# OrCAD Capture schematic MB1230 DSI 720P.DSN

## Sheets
1 mb1230: size A4; title: MB1230: 1280 x 720p DSI  LCD; rev: C02; company: ST MICROELECTRONICS; note: MB1230: 1280 x 720p DSI LCD; note: MDG/GPM
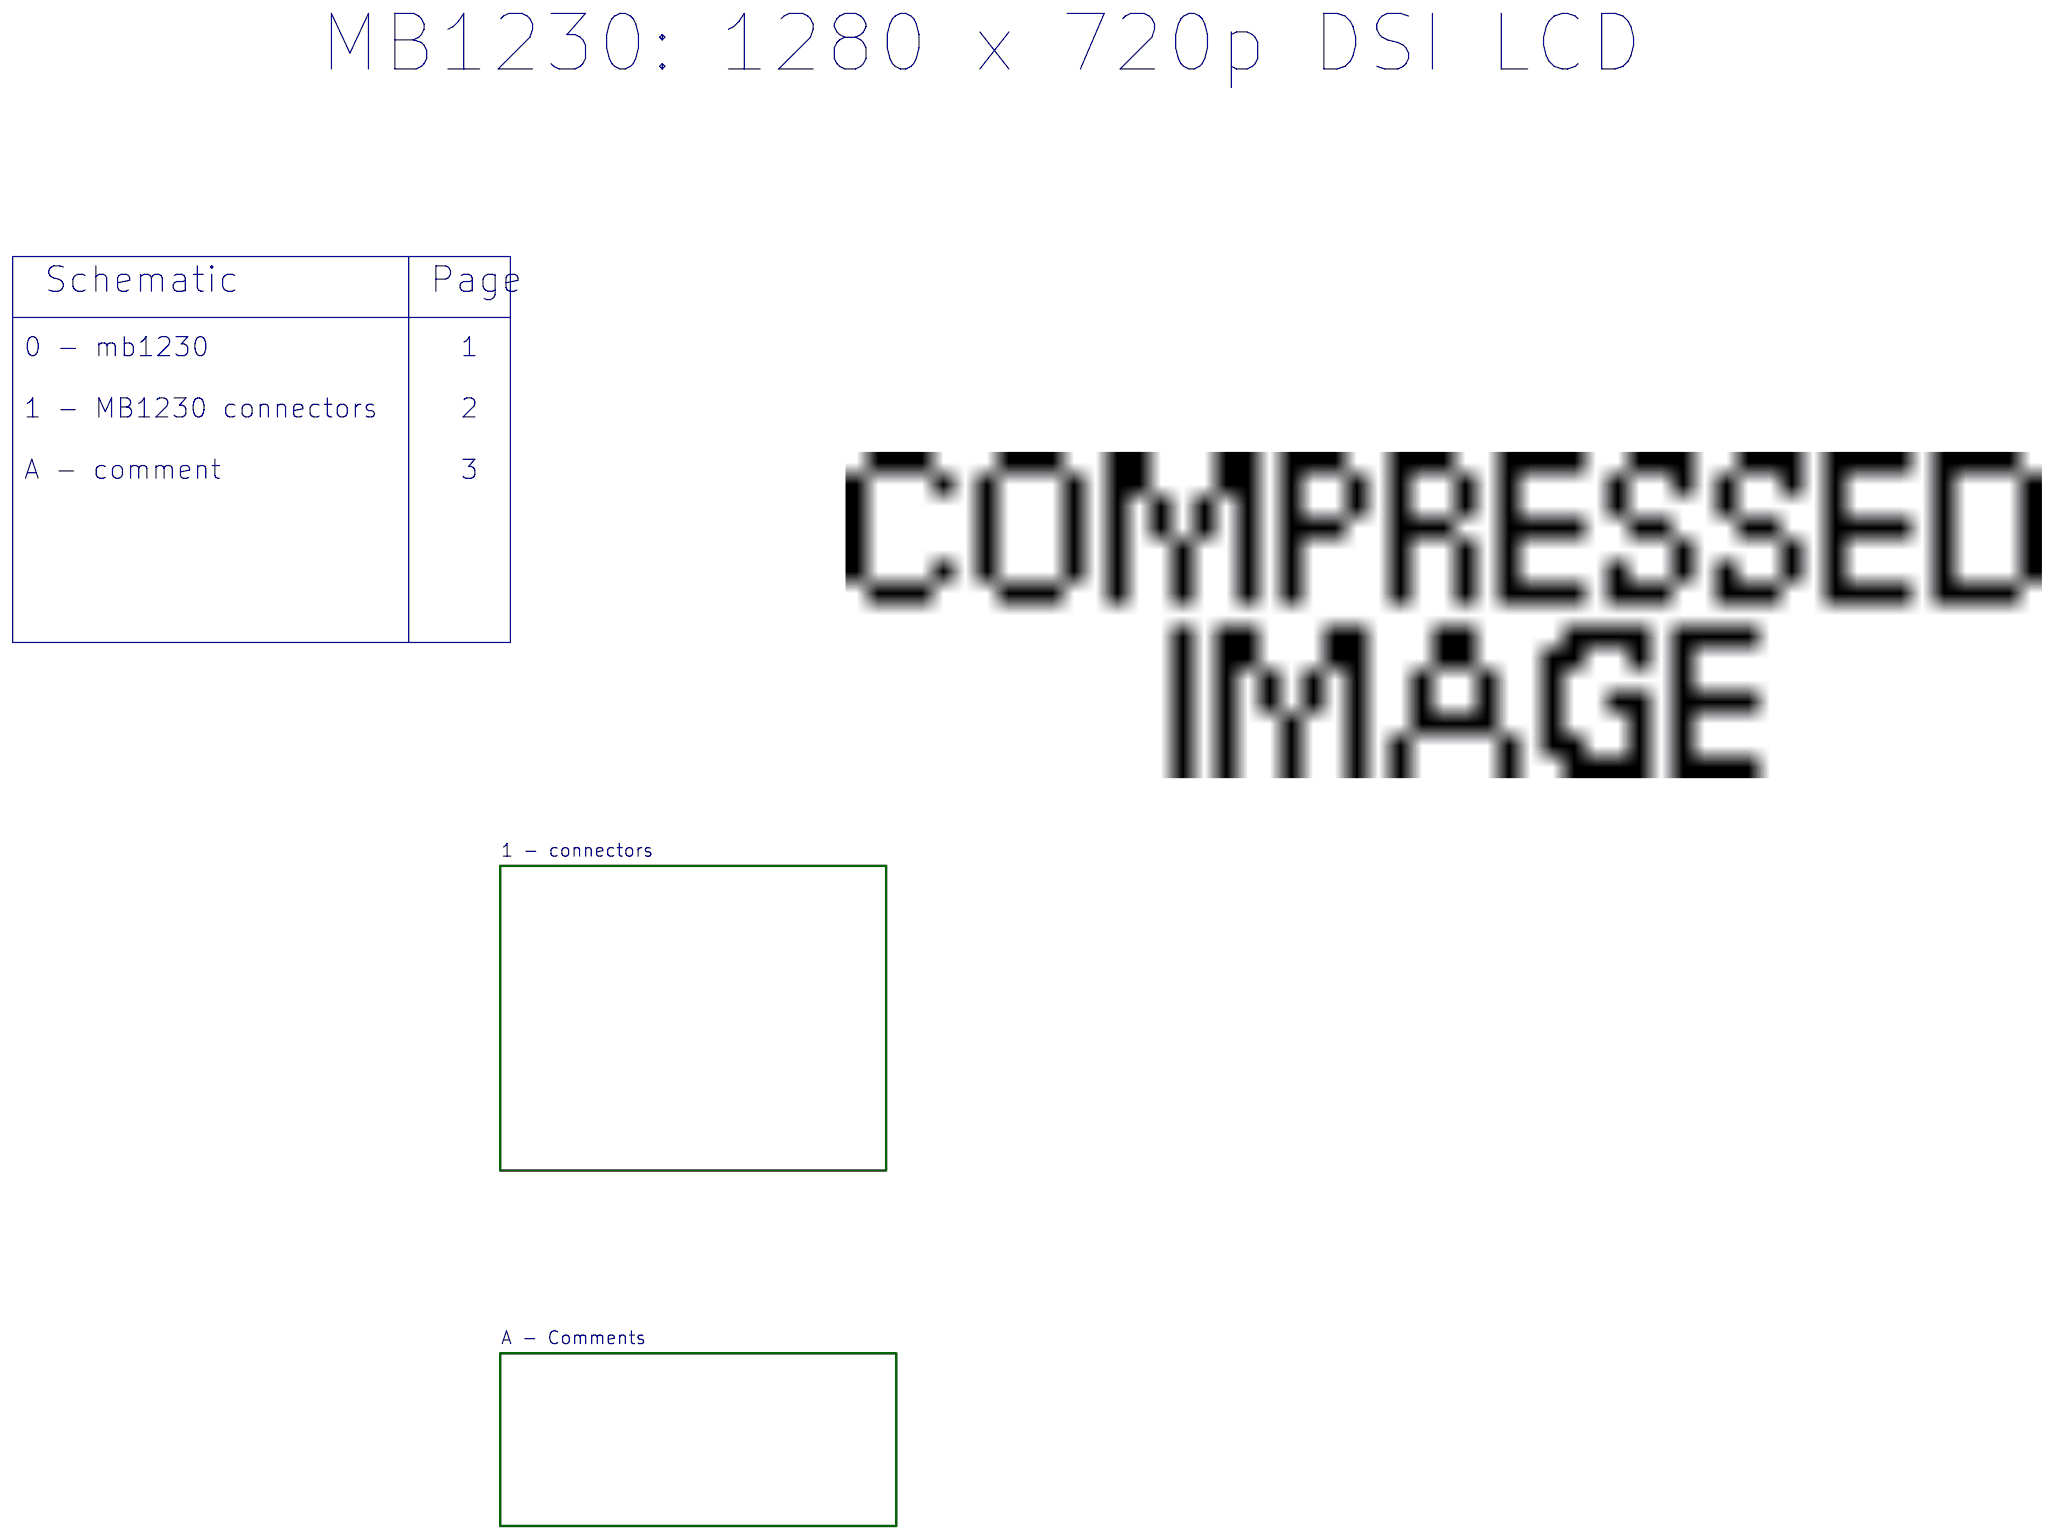
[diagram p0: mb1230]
2 A - Comments: note: A - Comments
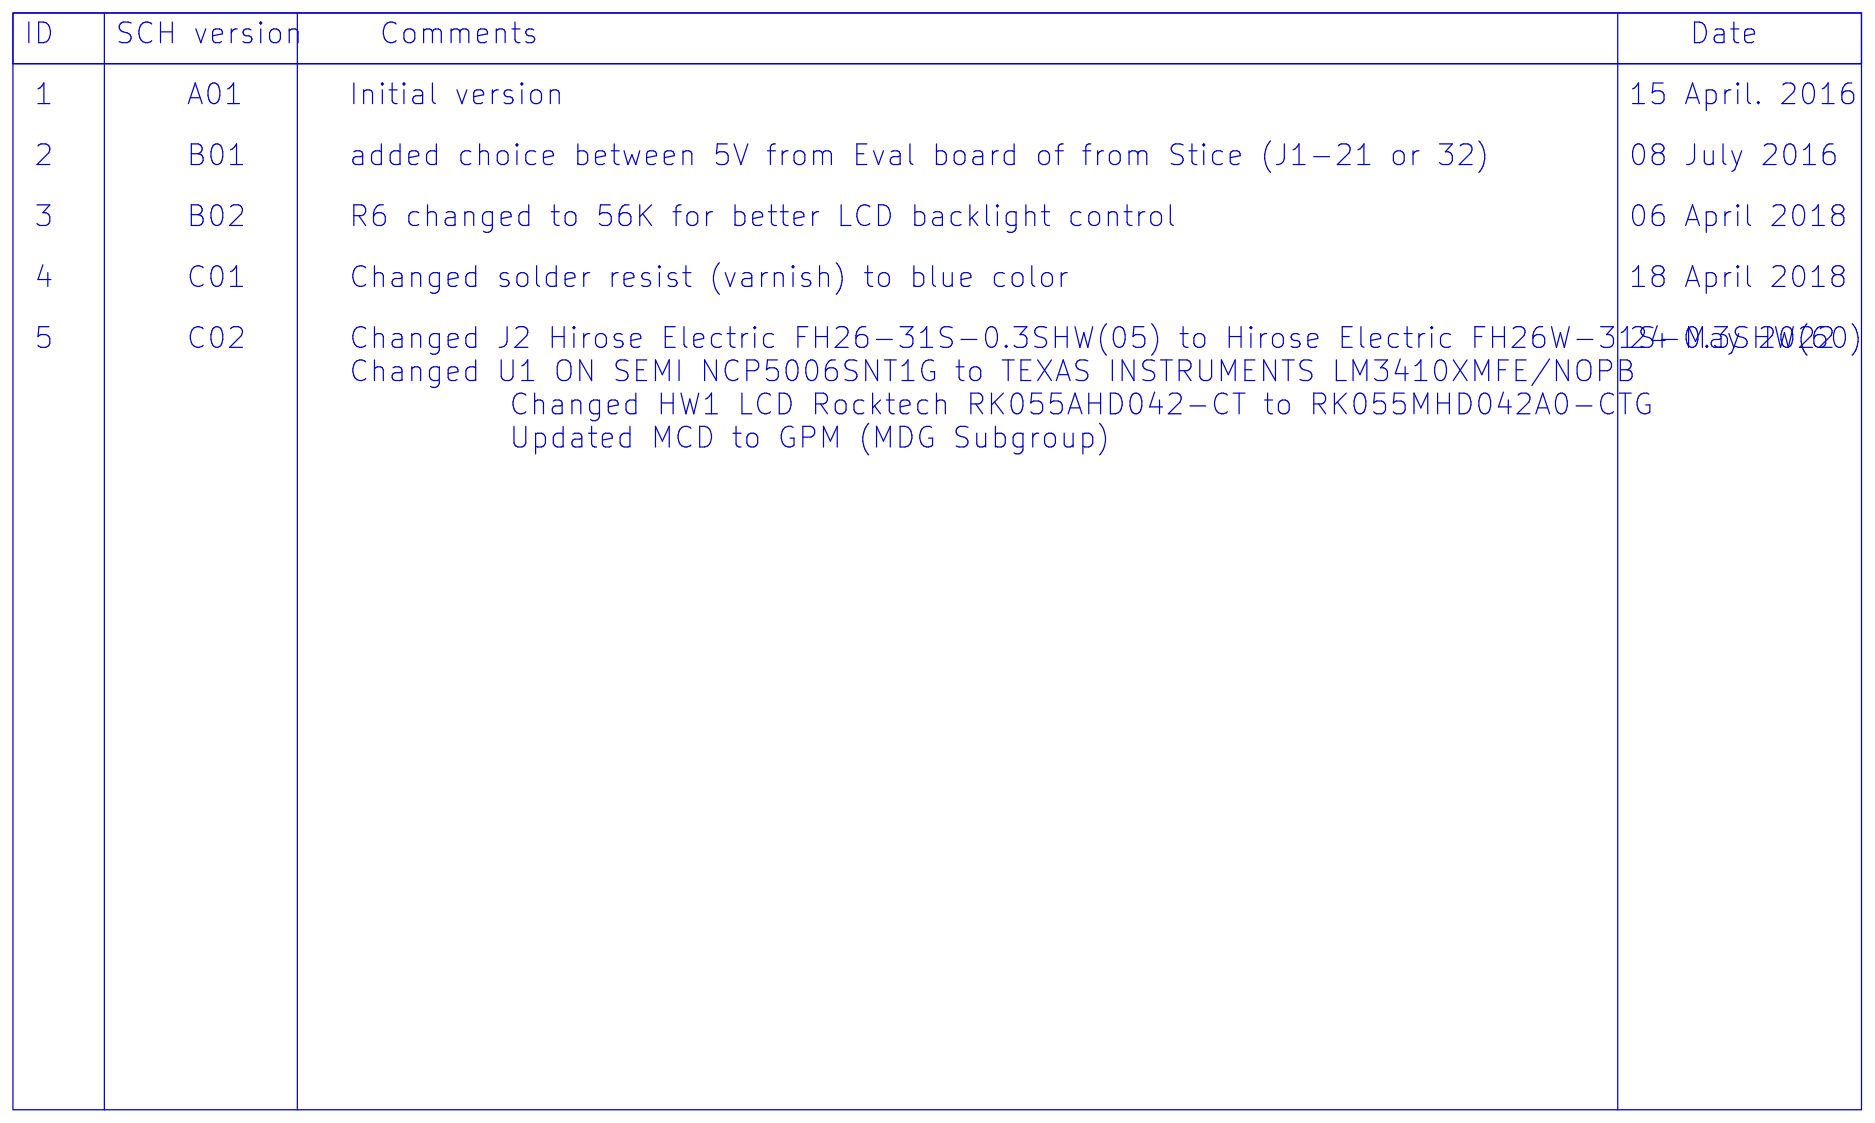
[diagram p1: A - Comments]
3 1 - connectors: size A3; note: Connectors; block 1 - connectors
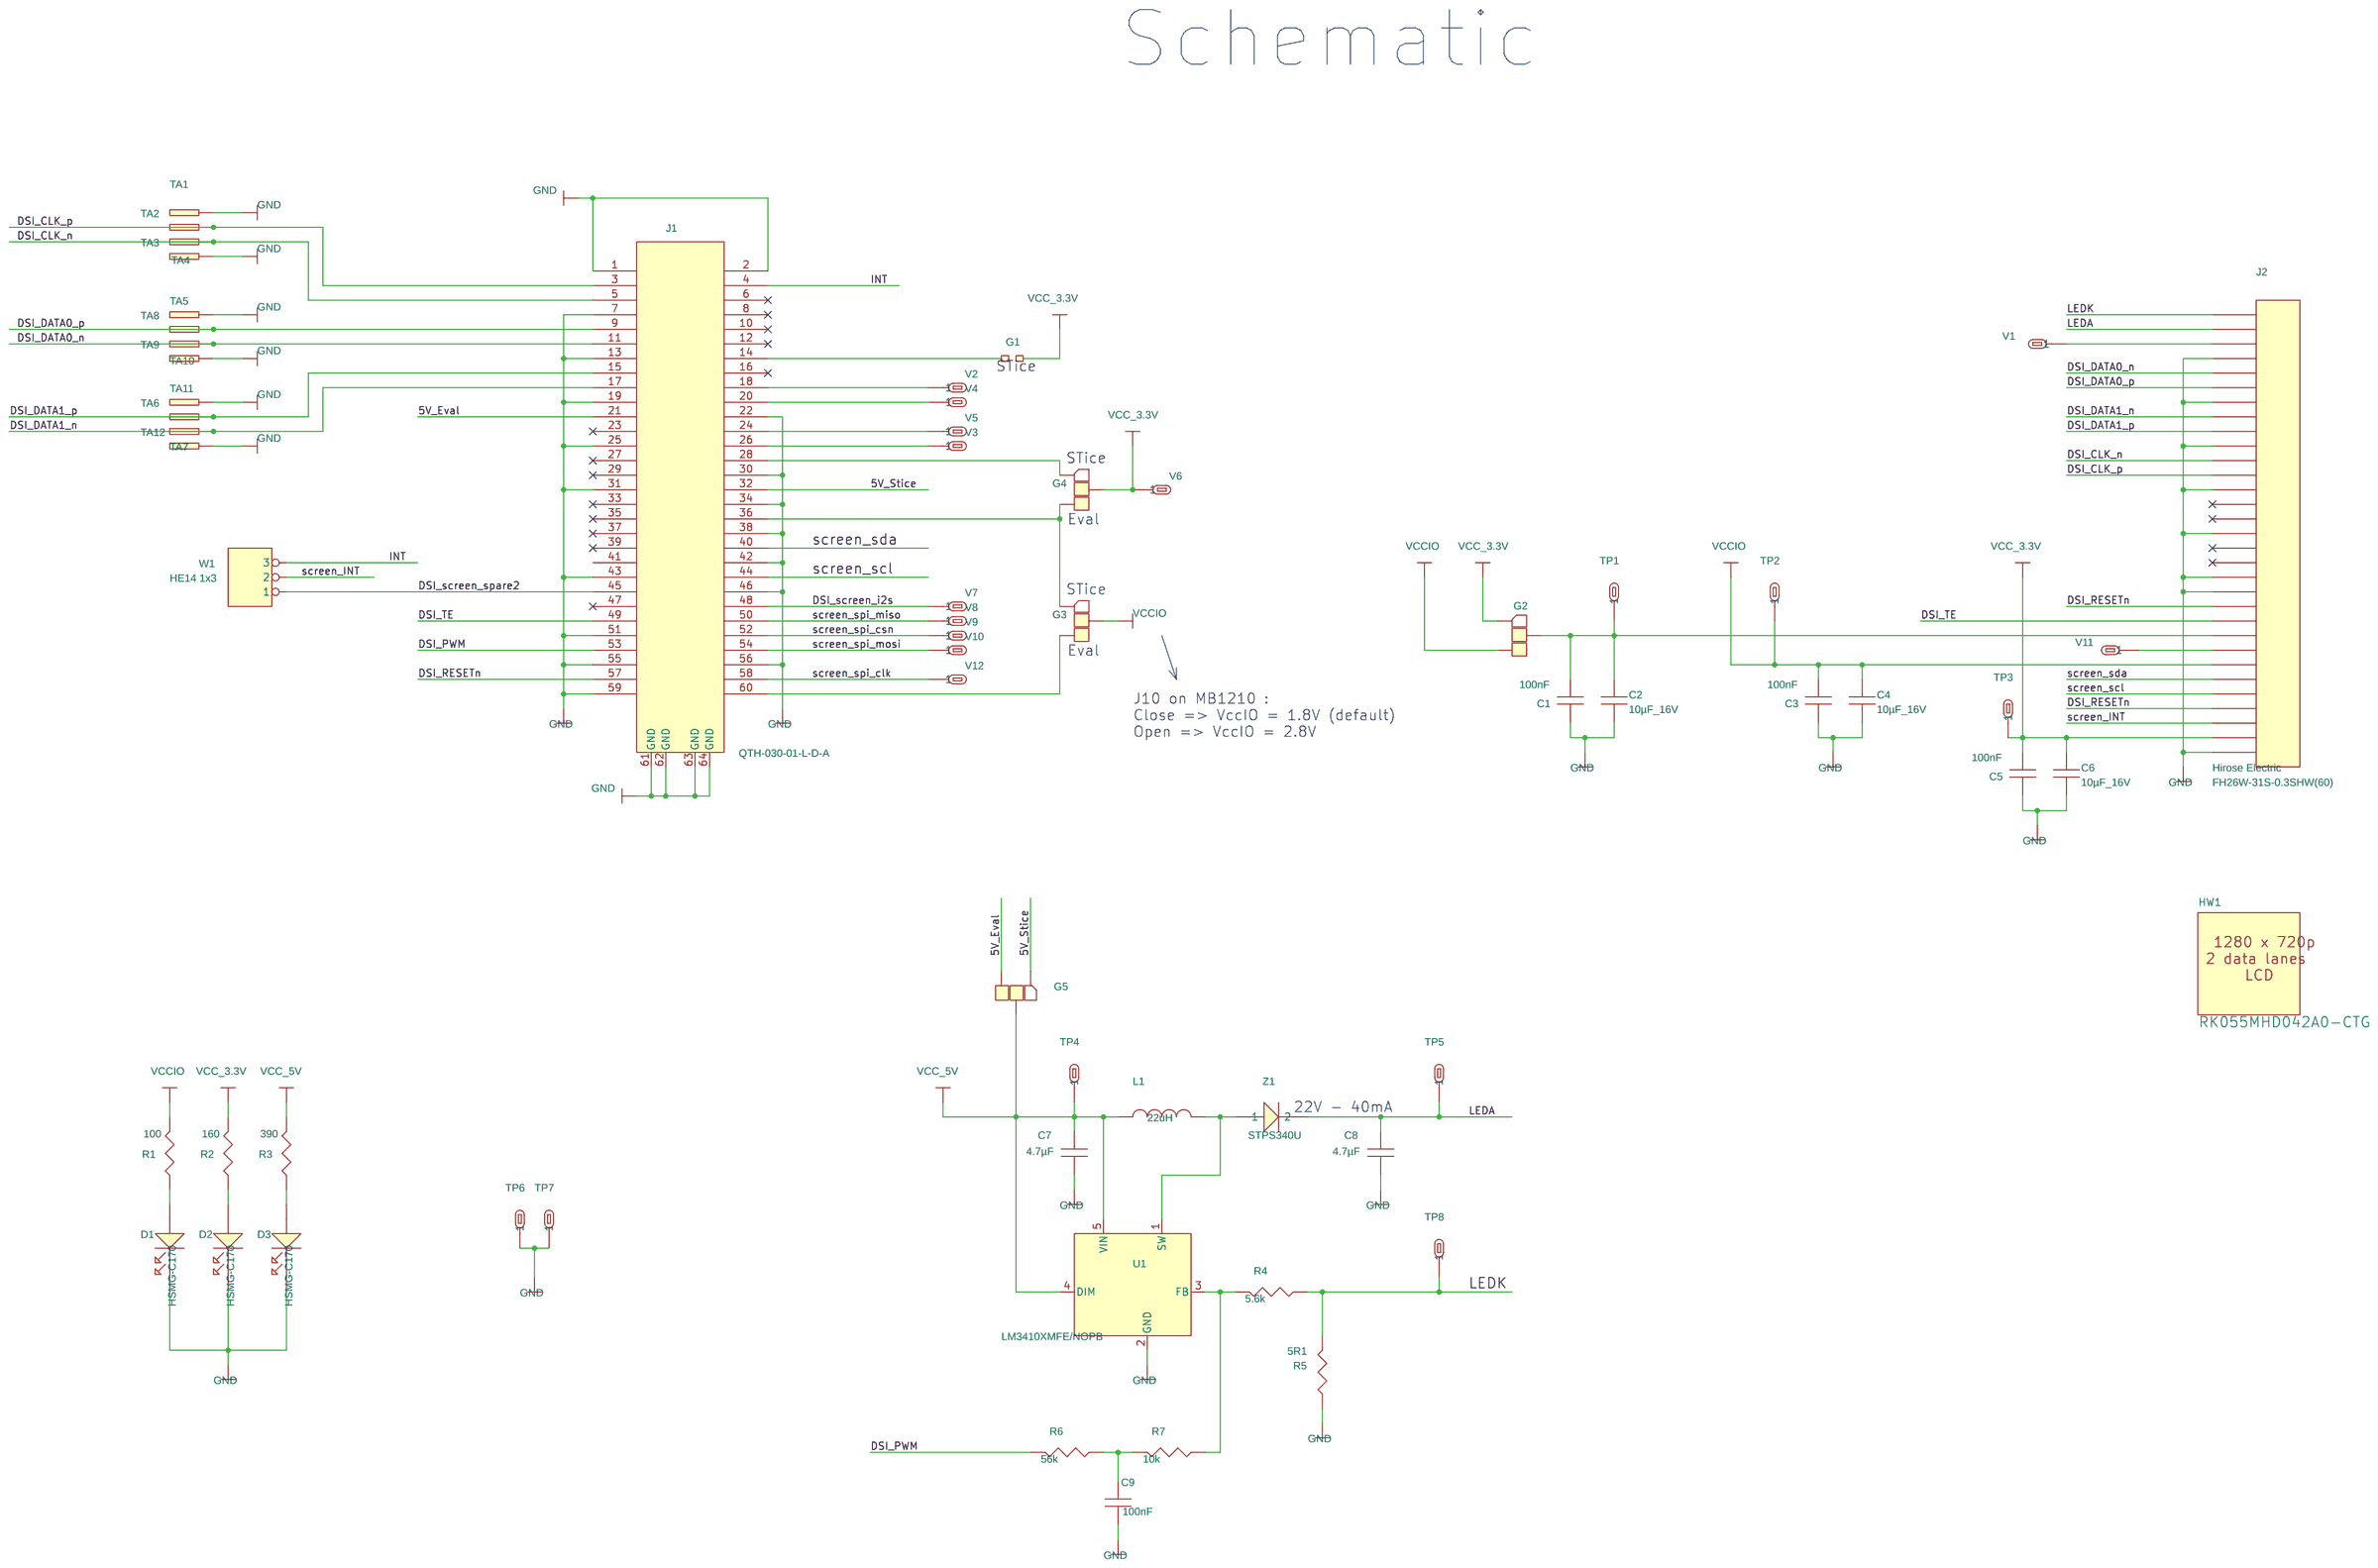
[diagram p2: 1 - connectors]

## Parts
C1  100nF  [0603RV]
C2  10µF_16V  [1210]
C3  100nF  [0603RV]
C4  10µF_16V  [1210]
C5  100nF  [0603RV]
C6  10µF_16V  [1210]
C7  4.7µF  [1210]
C8  4.7µF  [1210]
C9  100nF  [0603RV]
D1  HSMG-C170  [LED-SERIE-HSMx-C170]
D2  HSMG-C170  [LED-SERIE-HSMx-C170]
D3  HSMG-C170  [LED-SERIE-HSMx-C170]
G1  GDC2  [CAFEOUV0603]
G2  GDC3-1L  [CAFEOUV0603-3PTS]
G3  GDC3-1L  [CAFEOUV0603-3PTS]
G4  GDC3-1L  [CAFEOUV0603-3PTS]
G5  GDC3-1L  [CAFEOUV0603-3PTS]
HW1  RK055MHD042A0-CTG
J1  QTH-030-01-L-D-A  [QTH03001LDA]
J2  FH26W-31S-0.3SHW(60)  [CONN-HIROSE-FH26-31S-0.3SHW]
L1  22uH  [MMS1038]
R1  100  [0603RV]
R2  160  [0603RV]
R3  390  [0603RV]
R4  5.6k  [0603RV]
R5  5R1  [0603RV]
R6  56k  [0603RV]
R7  10k  [0603RV]
TA1  probe_Surface_Mount_Track  [TESTPOINT (CMS 40X40)]
TA2  probe_Surface_Mount_Track  [SONDE (CMS TRACK 120µm)]
TA3  probe_Surface_Mount_Track  [SONDE (CMS TRACK 120µm)]
TA4  probe_Surface_Mount_Track  [TESTPOINT (CMS 40X40)]
TA5  probe_Surface_Mount_Track  [TESTPOINT (CMS 40X40)]
TA6  probe_Surface_Mount_Track  [SONDE (CMS TRACK 120µm)]
TA7  probe_Surface_Mount_Track  [TESTPOINT (CMS 40X40)]
TA8  probe_Surface_Mount_Track  [SONDE (CMS TRACK 120µm)]
TA9  probe_Surface_Mount_Track  [SONDE (CMS TRACK 120µm)]
TA10  probe_Surface_Mount_Track  [TESTPOINT (CMS 40X40)]
TA11  probe_Surface_Mount_Track  [TESTPOINT (CMS 40X40)]
TA12  probe_Surface_Mount_Track  [SONDE (CMS TRACK 120µm)]
TP1  MW1X1C  [SICAX (1)]
TP2  MW1X1C  [SICAX (1)]
TP3  MW1X1C  [SICAX (1)]
TP4  MW1X1C  [SICAX (1)]
TP5  MW1X1C  [SICAX (1)]
TP6  MW1X1C  [SICAX (1)]
TP7  MW1X1C  [SICAX (1)]
TP8  MW1X1C  [SICAX (1)]
U1  LM3410XMFE/NOPB  [DFN8_DD_EXP]
V1  VIA  [TROU-0.4-VIA]
V2  VIA  [TROU-0.4-VIA]
V3  VIA  [TROU-0.4-VIA]
V4  VIA  [TROU-0.4-VIA]
V5  VIA  [TROU-0.4-VIA]
V6  VIA  [TROU-0.4-VIA]
V7  VIA  [TROU-0.4-VIA]
V8  VIA  [TROU-0.4-VIA]
V9  VIA  [TROU-0.4-VIA]
V10  VIA  [TROU-0.4-VIA]
V11  VIA  [TROU-0.4-VIA]
V12  VIA  [TROU-0.4-VIA]
W1  HE14 1x3  [SICAX (3)]
Z1  STPS340U  [DO214AA]

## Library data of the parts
C1 C3 C5 C9 = C22nF_X7R_50V_603: Ceramic Capacitor X7R 25V
C2 C4 C6 = C22µF_X5R_16V_1210: Ceramic Capacitor X7R 16V
C7 C8 = C22µF_X5R_16V_1210: Ceramic Capacitor X7R 50V
D1-D3 = LD_GREEN_0805: green led CMS
G1 = GDC2_2
G2-G5 = GDC3-1L
HW1 = HW_LCDHannstar_2: 1280 x 720p DSI 2 data lanes LCD; Manuf_1: Rocktech
J1 = QSH-030-01-L-D-A: Socket 2*30 (0.5mm) Hi-Speed; Distrib: AVNET
J2 = CON31: Connector; Distrib: FARNELL; Manuf_1: Hirose Electric
L1 = Ind_Coilcraft_MSS1038-382N: Inductor; Distrib: FARNELL; Manuf_1: COILCRAFT; Manuf_Part_1: MSS1038-223MLC; Order: 2288209
R1-R7 = 1M_0: Resistor 5%
TA1-TA12 = probe_Surface_Mount_Track_0
TP1-TP8 = MW1X1C: point de test; Manuf_1: VERO; Manuf_Part_1: 20-2137; Order: 8731128; distrib: FARNELL
U1 = LM3410XMFE_NOPB
V1-V12 = VIA
W1 = MW1X3C: Barrette 1x3 droit 2.54mm, male
Z1 = STPS340U: Power Schottky rectifier; Distrib: FARNELL; Manuf_1: STMicroelectronics; Order: 9803548

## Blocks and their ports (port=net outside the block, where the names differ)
1 - connectors = schematic 1 - connectors, on sheet 0 - mb1230: no ports
A - Comments = schematic A - Comments, on sheet 0 - mb1230: no ports

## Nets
1 - connectors/5V_Eval: G5.3 J1.21
1 - connectors/5V_Stice: G5.1 J1.32
GND: C1.2 C2.2 C3.2 C4.2 C5.2 C6.2 C7.2 C8.2 C9.2 D1.1 D2.1 D3.1 J1.1 J1.2 J1.7 J1.13 J1.19 J1.22 J1.25 J1.30 J1.31 J1.34 J1.38 J1.42 J1.43 J1.46 J1.51 J1.55 J1.56 J1.59 J1.61(GND) J1.62(GND) J1.63(GND) J1.64(GND) J2.4 J2.7 J2.10 J2.13 J2.16 J2.19 J2.20 J2.31 R5.2 TA1.1 TA4.1 TA5.1 TA7.1 TA10.1 TA11.1 TP6.1 TP7.1 U1.2(GND)
VCC_3.3V: C5.1 C6.1 G1.2 G2.1 G4.2 J2.30 R2.1 TP3.1 V6.1
VCC_5V: C7.1 G5.2 L1.1 R3.1 TP4.1 U1.4(DIM) U1.5(VIN)
VccIO: C3.1 C4.1 G2.3 G3.2 J2.25 R1.1 TP2.1
1 - connectors/DSI_CLK_n: J1.5 J2.11 TA3.1
1 - connectors/DSI_CLK_p: J1.3 J2.12 TA2.1
1 - connectors/DSI_DATA0_n: J1.11 J2.5 TA9.1
1 - connectors/DSI_DATA0_p: J1.9 J2.6 TA8.1
1 - connectors/DSI_DATA1_n: J1.17 J2.8 TA12.1
1 - connectors/DSI_DATA1_p: J1.15 J2.9 TA6.1
1 - connectors/DSI_PWM: J1.53 R6.1
1 - connectors/DSI_RESETn: J1.57 J2.21 J2.28
1 - connectors/DSI_screen_i2s: J1.48 V7.1
1 - connectors/DSI_screen_spare2: J1.45 W1.1
1 - connectors/DSI_TE: J1.49 J2.22
1 - connectors/INT: J1.4 W1.3
1 - connectors/LEDA: C8.1 J2.2 TP5.1 Z1.2
1 - connectors/LEDK: J2.1 R4.2 R5.1 TP8.1
1 - connectors/screen_INT: J2.29 W1.2
1 - connectors/screen_scl: J1.44 J2.27
1 - connectors/screen_sda: J1.40 J2.26
1 - connectors/screen_spi_clk: J1.58 V12.1
1 - connectors/screen_spi_csn: J1.52 V9.1
1 - connectors/screen_spi_miso: J1.50 V8.1
1 - connectors/screen_spi_mosi: J1.54 V10.1
1 - connectors/N17041724: J1.18 V2.1
1 - connectors/N17041735: J1.20 V4.1
1 - connectors/N17041737: J1.24 V5.1
1 - connectors/N17041739: J1.26 V3.1
1 - connectors/N17043980: J2.3 V1.1
1 - connectors/N17043991: C1.1 C2.1 G2.2 J2.23 TP1.1
1 - connectors/N17046396: L1.2 U1.1(SW) Z1.1
1 - connectors/N17047588: R4.1 R7.2 U1.3(FB)
1 - connectors/N17047794: C9.1 R6.2 R7.1
1 - connectors/N17049887: D1.2 R1.2
1 - connectors/N17051312: D2.2 R2.2
1 - connectors/N17051358: D3.2 R3.2
1 - connectors/N17068660: J2.24 V11.1
1 - connectors/N17073446: G1.1 J1.14
1 - connectors/N17075951: G3.3 J1.60
1 - connectors/N17075956: G3.1 G4.3 J1.36
1 - connectors/N17076472: G4.1 J1.28

Not connected (* = marked no-connect by the designer): J1 6* 8* 10* 12* 16* 23* 27* 29* 33* 35* 37* 39* 41 47*; J2 14* 15* 17* 18*

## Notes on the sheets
sheet 1
- MB1230: 1280 x 720p DSI LCD
- Schematic
- Page
- 0 - mb1230
  1 - MB1230 connectors
  A - comment
- 1
  2
  3
sheet 2
- ID
- SCH version
- Comments
- Date
- 1
- A01
- Initial version
- 15 April. 2016
- 2
- B01
- added choice between 5V from Eval board of from Stice (J1-21 or 32)
- 08 July 2016
- 3
- B02
- R6 changed to 56K for better LCD backlight control
- 06 April 2018
- 4
- C01
- Changed solder resist (varnish) to blue color
- 18 April 2018
- 5
- C02
- Changed J2 Hirose Electric FH26-31S-0.3SHW(05) to Hirose Electric FH26W-31S-0.3SHW(60)
  Changed U1 ON SEMI NCP5006SNT1G to TEXAS INSTRUMENTS LM3410XMFE/NOPB
  		Changed HW1 LCD Rocktech RK055AHD042-CT to RK055MHD042A0-CTG
  		Updated MCD to GPM (MDG Subgroup)
- 24 May 2022
sheet 3
- Schematic
- STice
- STice
- Eval
- STice
- Eval
- J10 on MB1210 :
  Close => VccIO = 1.8V (default)
  Open => VccIO = 2.8V
- 22V - 40mA
